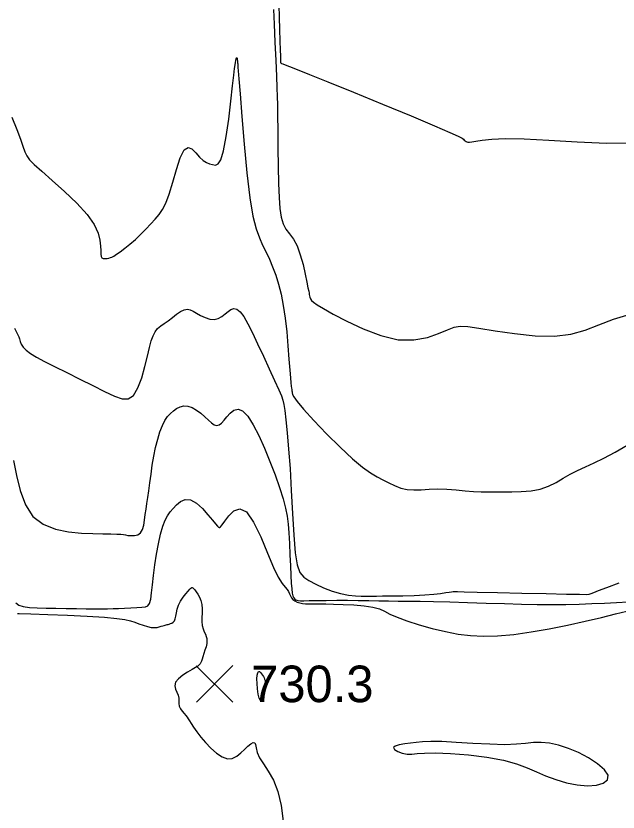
# Model space of a CAD drawing. Extents: x 2566142 to 2571431, y 418755 to 421584.
# Drawn here: x 2570718.9 to 2570965.9, y 419800.8 to 420127.5 of the extents above; entities that cross this region are included whole.
import ezdxf

# ---------------------------------------------------------------- set-up
doc = ezdxf.new("R2010")
doc.units = 0
for name, color, linetype in [('Contour_ADS_Major', 7, 'Continuous'), ('Contour_ADS_Minor', 7, 'Continuous'), ('Contour_ADS_Spot_Elevation', 7, 'Continuous')]:
    doc.layers.add(name, color=color, linetype=linetype)

# ---------------------------------------------------------------- blocks, each defined once
blk = doc.blocks.new('S750')
at = {"layer": 'Contour_ADS_Spot_Elevation'}
for p, q in [((-0.5, 0.498), (0.5, -0.498)), ((-0.498, -0.5), (0.498, 0.5))]:
    blk.add_line(p, q, dxfattribs=at)

msp = doc.modelspace()

# ---------------------------------------------------------------- linework, layer by layer
at = {"layer": 'Contour_ADS_Major'}
for points in [[(2570824.53, 420130.15), (2570824.8, 420124.09), (2570825.13, 420116.72), (2570825.46, 420109.22), (2570825.74, 420102.73), (2570825.93, 420098.04), (2570826.05, 420094.48), (2570826.13, 420091.01), (2570826.2, 420086.59), (2570826.29, 420080.49), (2570826.39, 420073.25), (2570826.52, 420065.71), (2570826.66, 420058.74)], [(2570826.66, 420058.74), (2570826.84, 420053), (2570827.13, 420048.47), (2570827.65, 420044.94), (2570828.48, 420042.2), (2570829.68, 420040.03), (2570831.14, 420038.06), (2570832.71, 420035.89), (2570834.22, 420033.13), (2570835.55, 420029.53), (2570836.66, 420025.49), (2570837.56, 420021.53), (2570838.23, 420018.21), (2570838.69, 420015.93), (2570838.98, 420014.52), (2570839.14, 420013.69), (2570839.23, 420013.15), (2570839.3, 420012.63), (2570839.44, 420012.08), (2570839.7, 420011.48), (2570840.18, 420010.81), (2570840.99, 420010.03), (2570842.47, 420008.96), (2570845, 420007.41), (2570848.96, 420005.19), (2570854.57, 420002.23), (2570861.34, 419999.06), (2570868.61, 419996.32), (2570875.73, 419994.67), (2570882.14, 419994.55), (2570887.68, 419995.59), (2570892.29, 419997.18), (2570895.9, 419998.73), (2570898.61, 419999.77), (2570901.11, 420000.2), (2570904.23, 420000.08), (2570908.83, 419999.42), (2570915.45, 419998.33), (2570923.44, 419997.14), (2570931.86, 419996.27), (2570939.77, 419996.12), (2570946.48, 419996.97), (2570952.35, 419998.63), (2570957.98, 420000.75), (2570963.99, 420003.02), (2570970.78, 420005.17)], [(2570719.6, 419882.33), (2570720.31, 419882.29), (2570725.09, 419882.14), (2570731.97, 419881.91), (2570740.06, 419881.59), (2570748.2, 419881.22), (2570755.22, 419880.79), (2570760.26, 419880.34), (2570763.61, 419879.85), (2570765.86, 419879.32), (2570767.62, 419878.73), (2570769.36, 419878.09), (2570771.12, 419877.47), (2570772.81, 419876.95), (2570774.34, 419876.62), (2570775.67, 419876.54), (2570776.78, 419876.64), (2570777.72, 419876.85), (2570778.49, 419877.09), (2570779.14, 419877.29), (2570779.69, 419877.45), (2570780.16, 419877.58), (2570780.59, 419877.68), (2570780.99, 419877.78), (2570781.4, 419877.87), (2570781.83, 419878), (2570782.31, 419878.16), (2570782.85, 419878.39), (2570783.4, 419878.75), (2570783.9, 419879.3), (2570784.28, 419880.1), (2570784.51, 419881.19), (2570784.72, 419882.54), (2570785.02, 419884.06), (2570785.57, 419885.69), (2570786.44, 419887.36), (2570787.52, 419888.96), (2570788.63, 419890.39), (2570789.58, 419891.53), (2570790.26, 419892.32), (2570790.7, 419892.78), (2570791, 419892.98), (2570791.23, 419892.98), (2570791.49, 419892.83), (2570791.82, 419892.5), (2570792.24, 419891.98), (2570792.79, 419891.24), (2570793.47, 419890.25), (2570794.19, 419889.03), (2570794.81, 419887.61), (2570795.22, 419886.02), (2570795.32, 419884.29), (2570795.24, 419882.49), (2570795.11, 419880.7), (2570795.1, 419879), (2570795.31, 419877.45), (2570795.7, 419876.07), (2570796.17, 419874.85), (2570796.62, 419873.79), (2570796.98, 419872.87), (2570797.21, 419872), (2570797.28, 419871.08), (2570797.17, 419870), (2570796.88, 419868.7), (2570796.46, 419867.27), (2570796.01, 419865.86), (2570795.59, 419864.6), (2570795.27, 419863.59), (2570795.02, 419862.81), (2570794.77, 419862.2), (2570794.48, 419861.7), (2570794.07, 419861.25), (2570793.46, 419860.77), (2570792.53, 419860.16), (2570791.17, 419859.34), (2570789.35, 419858.25), (2570787.37, 419856.96), (2570785.61, 419855.55), (2570784.43, 419854.09), (2570784.09, 419852.68), (2570784.38, 419851.31), (2570784.95, 419850.01), (2570785.47, 419848.76), (2570785.68, 419847.59), (2570785.69, 419846.46), (2570785.69, 419845.37), (2570785.87, 419844.3), (2570786.37, 419843.25), (2570787.08, 419842.23), (2570787.87, 419841.3), (2570788.58, 419840.49), (2570789.12, 419839.82), (2570789.57, 419839.16), (2570790.08, 419838.35), (2570790.79, 419837.23), (2570791.8, 419835.69), (2570793.13, 419833.8), (2570794.76, 419831.65), (2570796.67, 419829.36), (2570798.82, 419827.06), (2570801.12, 419825)], [(2570801.12, 419825), (2570803.44, 419823.45), (2570805.65, 419822.68), (2570807.67, 419822.86), (2570809.48, 419823.77), (2570811.14, 419825.12), (2570812.66, 419826.57), (2570814.05, 419827.86), (2570815.27, 419828.83), (2570816.25, 419829.34), (2570816.91, 419829.27), (2570817.24, 419828.52), (2570817.47, 419827.18), (2570817.9, 419825.35), (2570818.81, 419823.17), (2570820.39, 419820.67), (2570822.4, 419817.7), (2570824.49, 419813.99), (2570826.33, 419809.32), (2570827.65, 419803.57), (2570828.55, 419797.18)]]:
    msp.add_lwpolyline(points, dxfattribs=at)
msp.add_lwpolyline([(2570820.88, 419851.24), (2570820.55, 419849.65), (2570820.13, 419848.08), (2570819.67, 419846.95), (2570819.18, 419846.68), (2570818.71, 419847.56), (2570818.29, 419849.29), (2570817.97, 419851.47), (2570817.79, 419853.67), (2570817.77, 419855.53), (2570817.89, 419856.97), (2570818.13, 419857.96), (2570818.45, 419858.47), (2570818.84, 419858.5), (2570819.25, 419858.18), (2570819.67, 419857.63), (2570820.07, 419857.02), (2570820.41, 419856.45), (2570820.7, 419855.91), (2570820.93, 419855.39), (2570821.09, 419854.84), (2570821.18, 419854.24), (2570821.18, 419853.49), (2570821.08, 419852.52), (2570820.88, 419851.24)], close=True, dxfattribs=at)
at = {"layer": 'Contour_ADS_Minor'}
for points in [[(2570826.73, 420131.92), (2570826.88, 420127.03), (2570827.04, 420121.95), (2570827.19, 420117.26), (2570827.31, 420113.5), (2570827.39, 420111.09), (2570827.43, 420109.79), (2570827.45, 420109.22), (2570827.46, 420109), (2570827.46, 420108.81), (2570827.47, 420108.6), (2570827.49, 420108.41), (2570827.51, 420108.25), (2570827.57, 420108.14), (2570827.79, 420108.01), (2570828.35, 420107.79), (2570829.4, 420107.39), (2570831.18, 420106.7), (2570834.26, 420105.49), (2570839.29, 420103.48), (2570846.9, 420100.41), (2570857.36, 420096.16), (2570869.3, 420091.28), (2570880.96, 420086.48), (2570890.6, 420082.46), (2570896.89, 420079.74), (2570900.34, 420078.16), (2570901.87, 420077.33), (2570902.44, 420076.9), (2570902.82, 420076.56), (2570903.17, 420076.27), (2570903.52, 420076.03), (2570903.87, 420075.86), (2570904.26, 420075.76), (2570904.88, 420075.76), (2570905.93, 420075.89), (2570907.61, 420076.16), (2570910.18, 420076.58), (2570914.04, 420076.98), (2570919.64, 420077.21), (2570927.4, 420077.08), (2570937.53, 420076.51), (2570949.15, 420075.79), (2570961.16, 420075.31), (2570972.43, 420075.44)], [(2570717.19, 420085.91), (2570719.3, 420080.9), (2570720.76, 420077), (2570721.78, 420074.03), (2570722.57, 420071.78), (2570723.37, 420070.05), (2570724.54, 420068.43), (2570726.45, 420066.48), (2570729.48, 420063.76), (2570733.82, 420059.98), (2570738.89, 420055.46), (2570743.92, 420050.64), (2570748.15, 420045.99), (2570750.99, 420041.88), (2570752.62, 420038.37), (2570753.38, 420035.44), (2570753.64, 420033.06), (2570753.71, 420031.2), (2570753.74, 420029.82), (2570753.85, 420028.86), (2570754.16, 420028.27), (2570754.74, 420027.99), (2570755.5, 420027.94), (2570756.32, 420028.03), (2570757.07, 420028.18), (2570757.67, 420028.34), (2570758.27, 420028.57), (2570759.02, 420028.99), (2570760.1, 420029.7), (2570761.64, 420030.78), (2570763.56, 420032.21), (2570765.7, 420033.91), (2570767.94, 420035.84), (2570770.14, 420037.92), (2570772.24, 420040.06), (2570774.22, 420042.18), (2570776.01, 420044.17), (2570777.61, 420046.03), (2570779.06, 420048.08), (2570780.43, 420050.73), (2570781.81, 420054.39), (2570783.25, 420059.24), (2570784.74, 420064.53), (2570786.29, 420069.28), (2570787.88, 420072.52), (2570789.5, 420073.57), (2570791.11, 420072.91), (2570792.7, 420071.3), (2570794.24, 420069.54), (2570795.69, 420068.24), (2570797.06, 420067.4), (2570798.36, 420066.88), (2570799.59, 420066.53), (2570800.76, 420066.33), (2570801.88, 420066.77), (2570802.98, 420068.5), (2570804.06, 420072.13), (2570805.14, 420077.99), (2570806.17, 420085.2), (2570807.07, 420092.56), (2570807.79, 420098.86), (2570808.28, 420103.21), (2570808.59, 420105.87), (2570808.79, 420107.39), (2570808.92, 420108.34), (2570809.06, 420109.17), (2570809.2, 420109.87), (2570809.34, 420110.34), (2570809.47, 420110.47)], [(2570809.47, 420110.47), (2570809.59, 420110.21), (2570809.68, 420109.66), (2570809.77, 420108.98), (2570809.83, 420108.32), (2570809.88, 420107.8), (2570809.91, 420107.4), (2570809.93, 420107.08), (2570809.95, 420106.79), (2570809.98, 420106.34), (2570810.09, 420104.94), (2570810.35, 420101.67), (2570810.82, 420095.6), (2570811.56, 420086.23), (2570812.53, 420074.84), (2570813.65, 420063.16), (2570814.87, 420052.88), (2570816.13, 420045.32), (2570817.42, 420040.09), (2570818.75, 420036.4), (2570820.1, 420033.47), (2570821.49, 420030.62), (2570822.86, 420027.65), (2570824.2, 420024.51), (2570825.46, 420021.11), (2570826.61, 420017.39), (2570827.65, 420013.28), (2570828.56, 420008.68), (2570829.34, 420003.54), (2570829.98, 419997.87), (2570830.5, 419992.09), (2570830.91, 419986.7), (2570831.25, 419982.23), (2570831.51, 419979.03), (2570831.71, 419976.95), (2570831.87, 419975.65), (2570831.99, 419974.84), (2570832.07, 419974.24), (2570832.14, 419973.74), (2570832.18, 419973.29), (2570832.22, 419972.83), (2570832.32, 419972.24), (2570832.85, 419971.19), (2570834.23, 419969.27), (2570836.91, 419966.1), (2570841.12, 419961.49), (2570846.34, 419956.03), (2570851.85, 419950.51), (2570856.94, 419945.74), (2570861.06, 419942.31), (2570864.32, 419940.01), (2570867.02, 419938.43), (2570869.44, 419937.19), (2570871.81, 419935.95), (2570874.23, 419934.78), (2570876.73, 419933.81), (2570879.36, 419933.2), (2570882.17, 419933.02), (2570885.17, 419933.13), (2570888.4, 419933.35), (2570891.88, 419933.47), (2570895.6, 419933.36), (2570899.41, 419933.06), (2570903.14, 419932.71), (2570906.59, 419932.41), (2570909.67, 419932.25), (2570912.54, 419932.21), (2570915.45, 419932.22), (2570918.64, 419932.24), (2570922.27, 419932.23), (2570926.2, 419932.32), (2570930.17, 419932.65), (2570933.94, 419933.36), (2570937.35, 419934.56), (2570940.45, 419936.1), (2570943.39, 419937.8), (2570946.29, 419939.48), (2570949.28, 419941.02), (2570952.49, 419942.52), (2570956.05, 419944.16), (2570960.08, 419946.11), (2570964.65, 419948.52), (2570969.55, 419951.41)], [(2570718.28, 419999.36), (2570719.18, 419997.8), (2570719.75, 419996.7), (2570720.1, 419995.82), (2570720.36, 419994.98), (2570720.64, 419993.99), (2570721.1, 419992.87), (2570721.87, 419991.64), (2570723.09, 419990.34), (2570724.91, 419988.98), (2570727.42, 419987.49), (2570730.68, 419985.75), (2570734.79, 419983.67), (2570739.73, 419981.19), (2570745.11, 419978.5), (2570750.46, 419975.82), (2570755.31, 419973.39), (2570759.28, 419971.47), (2570762.45, 419970.35), (2570765.01, 419970.36), (2570767.12, 419971.83), (2570768.95, 419974.89), (2570770.51, 419979.06), (2570771.83, 419983.63), (2570772.89, 419987.95), (2570773.73, 419991.46), (2570774.44, 419994.19), (2570775.15, 419996.28), (2570775.99, 419997.9), (2570777.04, 419999.19), (2570778.32, 420000.29), (2570779.77, 420001.34), (2570781.37, 420002.47), (2570783.07, 420003.76), (2570784.8, 420005.07), (2570786.45, 420006.2), (2570787.94, 420006.94), (2570789.22, 420007.16), (2570790.38, 420006.91), (2570791.59, 420006.32), (2570792.98, 420005.5), (2570794.65, 420004.58), (2570796.52, 420003.73), (2570798.44, 420003.13), (2570800.27, 420002.98), (2570801.9, 420003.38), (2570803.35, 420004.19), (2570804.67, 420005.21), (2570805.9, 420006.22), (2570807.08, 420007.02), (2570808.28, 420007.4), (2570809.52, 420007.17), (2570810.87, 420006.13), (2570812.36, 420004.13), (2570814.03, 420001.21), (2570815.91, 419997.47), (2570818.03, 419992.98), (2570820.39, 419987.91), (2570822.78, 419982.73), (2570824.97, 419977.97), (2570826.7, 419974.16), (2570827.81, 419971.63), (2570828.44, 419969.85), (2570828.81, 419968.08), (2570829.14, 419965.57), (2570829.59, 419961.73), (2570830.15, 419956.46), (2570830.76, 419949.81), (2570831.35, 419941.84), (2570831.86, 419932.73), (2570832.36, 419923.3), (2570832.88, 419914.49), (2570833.51, 419907.27), (2570834.3, 419902.3), (2570835.39, 419899.2), (2570836.93, 419897.27), (2570839.06, 419895.84), (2570841.86, 419894.37), (2570845.13, 419892.89), (2570848.63, 419891.54), (2570852.1, 419890.49), (2570855.31, 419889.84), (2570858.16, 419889.54), (2570860.57, 419889.45), (2570862.46, 419889.46), (2570863.84, 419889.48), (2570865.11, 419889.49), (2570866.77, 419889.49), (2570869.3, 419889.51), (2570873.02, 419889.55), (2570877.54, 419889.62), (2570882.28, 419889.75), (2570886.69, 419889.95), (2570890.3, 419890.24), (2570893.1, 419890.56), (2570895.18, 419890.88), (2570896.65, 419891.13), (2570897.61, 419891.28), (2570898.18, 419891.35), (2570898.47, 419891.37)], [(2570717.88, 419945.07), (2570719.14, 419938.98), (2570720.66, 419932.74), (2570722.79, 419926.94), (2570725.87, 419922.18), (2570730.09, 419918.91), (2570735.13, 419916.91), (2570740.5, 419915.84), (2570745.75, 419915.34), (2570750.47, 419915.09), (2570754.51, 419914.99), (2570757.82, 419914.95), (2570760.3, 419914.92), (2570761.97, 419914.84), (2570763.07, 419914.72), (2570763.92, 419914.56), (2570764.84, 419914.39), (2570766.06, 419914.26), (2570767.48, 419914.28), (2570768.88, 419914.61), (2570770.06, 419915.41), (2570770.86, 419916.77), (2570771.36, 419918.58), (2570771.69, 419920.68), (2570771.96, 419922.89), (2570772.28, 419925.11), (2570772.66, 419927.4), (2570773.06, 419929.89), (2570773.48, 419932.7), (2570773.89, 419935.93), (2570774.34, 419939.46), (2570774.85, 419943.15), (2570775.46, 419946.87), (2570776.2, 419950.46), (2570777.06, 419953.83), (2570778, 419956.85), (2570779, 419959.42), (2570780.03, 419961.47), (2570781.12, 419963.09), (2570782.26, 419964.37), (2570783.49, 419965.45), (2570784.81, 419966.38), (2570786.24, 419967.11), (2570787.77, 419967.49), (2570789.43, 419967.42), (2570791.2, 419966.81), (2570793.01, 419965.78), (2570794.77, 419964.48), (2570796.41, 419963.07), (2570797.84, 419961.71), (2570799.1, 419960.54), (2570800.22, 419959.72), (2570801.26, 419959.4), (2570802.25, 419959.68), (2570803.24, 419960.47), (2570804.3, 419961.64), (2570805.47, 419963.06), (2570806.81, 419964.55), (2570808.32, 419965.72), (2570810.02, 419966.16), (2570811.91, 419965.43), (2570813.99, 419963.24), (2570816.2, 419959.76), (2570818.5, 419955.32), (2570820.81, 419950.21), (2570823.07, 419944.75), (2570825.18, 419939.26), (2570827.02, 419934.05), (2570828.5, 419929.43), (2570829.53, 419925.61), (2570830.19, 419922.28), (2570830.59, 419919.01), (2570830.86, 419915.38), (2570831.08, 419911.09), (2570831.29, 419906.45), (2570831.48, 419901.9), (2570831.67, 419897.87), (2570831.85, 419894.72), (2570832.04, 419892.38), (2570832.27, 419890.7), (2570832.54, 419889.53), (2570832.86, 419888.73), (2570833.25, 419888.21), (2570833.68, 419887.9), (2570834.17, 419887.73), (2570834.73, 419887.63), (2570835.59, 419887.57), (2570836.98, 419887.57), (2570839.16, 419887.6), (2570842.29, 419887.65), (2570846.16, 419887.71), (2570850.47, 419887.76), (2570854.95, 419887.76), (2570859.34, 419887.72), (2570863.61, 419887.63), (2570867.75, 419887.54), (2570871.78, 419887.47)], [(2570718.9, 419886.7), (2570720.1, 419885.8), (2570721.9, 419885.17), (2570724.42, 419884.8), (2570727.59, 419884.62), (2570731.26, 419884.56), (2570735.29, 419884.52), (2570739.52, 419884.44), (2570743.73, 419884.34), (2570747.7, 419884.24), (2570751.21, 419884.18), (2570754.09, 419884.18), (2570756.51, 419884.23), (2570758.74, 419884.32), (2570761.01, 419884.42), (2570763.51, 419884.52), (2570766.07, 419884.63), (2570768.48, 419884.74), (2570770.52, 419884.88), (2570772.01, 419885.08), (2570773.03, 419885.53), (2570773.71, 419886.48), (2570774.18, 419888.17), (2570774.56, 419890.74), (2570774.92, 419894.08), (2570775.34, 419897.98), (2570775.86, 419902.23), (2570776.55, 419906.63), (2570777.36, 419910.91), (2570778.25, 419914.83), (2570779.19, 419918.11), (2570780.13, 419920.59), (2570781.12, 419922.46), (2570782.2, 419923.97), (2570783.42, 419925.42), (2570784.83, 419926.96), (2570786.46, 419928.32), (2570788.34, 419929.1), (2570790.49, 419928.91), (2570792.91, 419927.53), (2570795.4, 419925.34), (2570797.69, 419922.87), (2570799.56, 419920.65), (2570800.81, 419919.12), (2570801.56, 419918.21), (2570801.97, 419917.76), (2570802.21, 419917.59), (2570802.43, 419917.6), (2570802.8, 419917.91), (2570803.46, 419918.72), (2570804.56, 419920.22), (2570806.19, 419922.41), (2570808.3, 419924.45), (2570810.78, 419925.32), (2570813.52, 419924), (2570816.41, 419919.83), (2570819.31, 419913.77), (2570822.05, 419907.13), (2570824.49, 419901.26), (2570826.5, 419897.17), (2570828.09, 419894.65), (2570829.3, 419893.17), (2570830.16, 419892.19), (2570830.73, 419891.3), (2570831.13, 419890.41), (2570831.48, 419889.56), (2570831.91, 419888.78), (2570832.52, 419888.09), (2570833.31, 419887.5), (2570834.24, 419887.02), (2570835.3, 419886.67), (2570836.46, 419886.44), (2570837.71, 419886.31), (2570839.03, 419886.26), (2570840.43, 419886.25), (2570841.94, 419886.26), (2570843.75, 419886.26), (2570846.07, 419886.25), (2570849.15, 419886.19), (2570853.08, 419886.08), (2570857.44, 419885.87), (2570861.71, 419885.52), (2570865.34, 419884.99), (2570868, 419884.24), (2570870.12, 419883.28), (2570872.32, 419882.11), (2570875.22, 419880.77), (2570879.28, 419879.26), (2570884.24, 419877.7), (2570889.66, 419876.21), (2570895.11, 419874.91), (2570900.28, 419873.91), (2570905.36, 419873.26), (2570910.66, 419872.99), (2570916.49, 419873.16), (2570923.07, 419873.77), (2570930.21, 419874.75), (2570937.66, 419876.03), (2570945.13, 419877.52)], [(2570898.47, 419891.37), (2570898.63, 419891.36), (2570898.89, 419891.35), (2570899.98, 419891.33), (2570902.77, 419891.26), (2570908.1, 419891.14), (2570916.4, 419890.94), (2570926.4, 419890.7), (2570936.39, 419890.47), (2570944.69, 419890.29), (2570950.01, 419890.2), (2570952.81, 419890.18), (2570953.97, 419890.24), (2570954.39, 419890.36), (2570954.86, 419890.55), (2570955.89, 419890.94), (2570957.9, 419891.71), (2570961.3, 419892.99), (2570966.3, 419894.92)], [(2570871.78, 419887.47), (2570875.75, 419887.44), (2570879.94, 419887.42), (2570884.65, 419887.37), (2570890.22, 419887.27), (2570896.83, 419887.08), (2570904.17, 419886.85), (2570911.8, 419886.59), (2570919.27, 419886.36), (2570926.23, 419886.19), (2570932.68, 419886.08), (2570938.72, 419886.04), (2570944.43, 419886.08), (2570949.9, 419886.2), (2570955.16, 419886.38), (2570960.25, 419886.6), (2570965.19, 419886.86), (2570969.98, 419887.14)], [(2570945.13, 419877.52), (2570952.36, 419879.12), (2570959.02, 419880.7), (2570964.82, 419882.13), (2570969.43, 419883.25)]]:
    msp.add_lwpolyline(points, dxfattribs=at)
msp.add_lwpolyline([(2570880.78, 419829.14), (2570878.37, 419828.79), (2570876.14, 419828.4), (2570874.46, 419827.92), (2570873.71, 419827.3), (2570874.14, 419826.53), (2570875.49, 419825.73), (2570877.36, 419825.05), (2570879.36, 419824.65), (2570881.24, 419824.63), (2570883.42, 419824.84), (2570886.46, 419825.08), (2570890.93, 419825.15), (2570897.17, 419824.89), (2570904.49, 419824.28), (2570912.02, 419823.36), (2570918.83, 419822.15), (2570924.26, 419820.69), (2570928.61, 419819.07), (2570932.4, 419817.38), (2570936.17, 419815.72), (2570940.32, 419814.19), (2570944.72, 419812.91), (2570949.13, 419812.03), (2570953.3, 419811.66), (2570956.98, 419811.91), (2570959.83, 419812.75), (2570961.54, 419814.13), (2570961.76, 419815.98), (2570960.3, 419818.21), (2570957.48, 419820.65), (2570953.78, 419823.06), (2570949.66, 419825.23), (2570945.51, 419826.97), (2570941.5, 419828.25), (2570937.73, 419829.07), (2570934.28, 419829.43), (2570931.16, 419829.36), (2570927.97, 419829.04), (2570924.21, 419828.68), (2570919.4, 419828.5), (2570913.26, 419828.65), (2570906.36, 419829.02), (2570899.53, 419829.44), (2570893.56, 419829.76), (2570889.04, 419829.84), (2570885.71, 419829.72), (2570883.11, 419829.46), (2570880.78, 419829.14)], close=True, dxfattribs=at)

# ---------------------------------------------------------------- block references
at = {"layer": 'Contour_ADS_Spot_Elevation', "xscale": 15, "yscale": 15}
msp.add_blockref('S750', (2570800.38, 419853.45), dxfattribs=at)

# ---------------------------------------------------------------- texts
at = {"layer": 'Contour_ADS_Spot_Elevation'}
msp.add_text('730.3', height=15, dxfattribs=at).set_placement((2570815.38, 419845.95))

doc.saveas('drawing.dxf')
